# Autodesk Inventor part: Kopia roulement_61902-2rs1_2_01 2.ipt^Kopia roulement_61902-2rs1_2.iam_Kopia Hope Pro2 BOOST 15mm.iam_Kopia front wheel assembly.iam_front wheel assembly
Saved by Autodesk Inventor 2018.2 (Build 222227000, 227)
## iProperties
Created: 2017-09
Part Number: Kopia roulement_61902-2rs1_2_01 2.ipt^Kopia roulement_61902-2rs1_2.iam_Kopia Hope Pro2 BOOST 15mm.iam_Kopia front wheel assembly.iam_front wheel assembly
Material: Ogólny
Document SubType Name: Modeling
Designer: Tomasz
Density: 1 g/cm^3
Appearance: Domyślna
Author: Tomasz
Sending System: SolidWorks 2017
Last Author: Tomasz
Last Saved: 2017-09-11
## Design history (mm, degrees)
